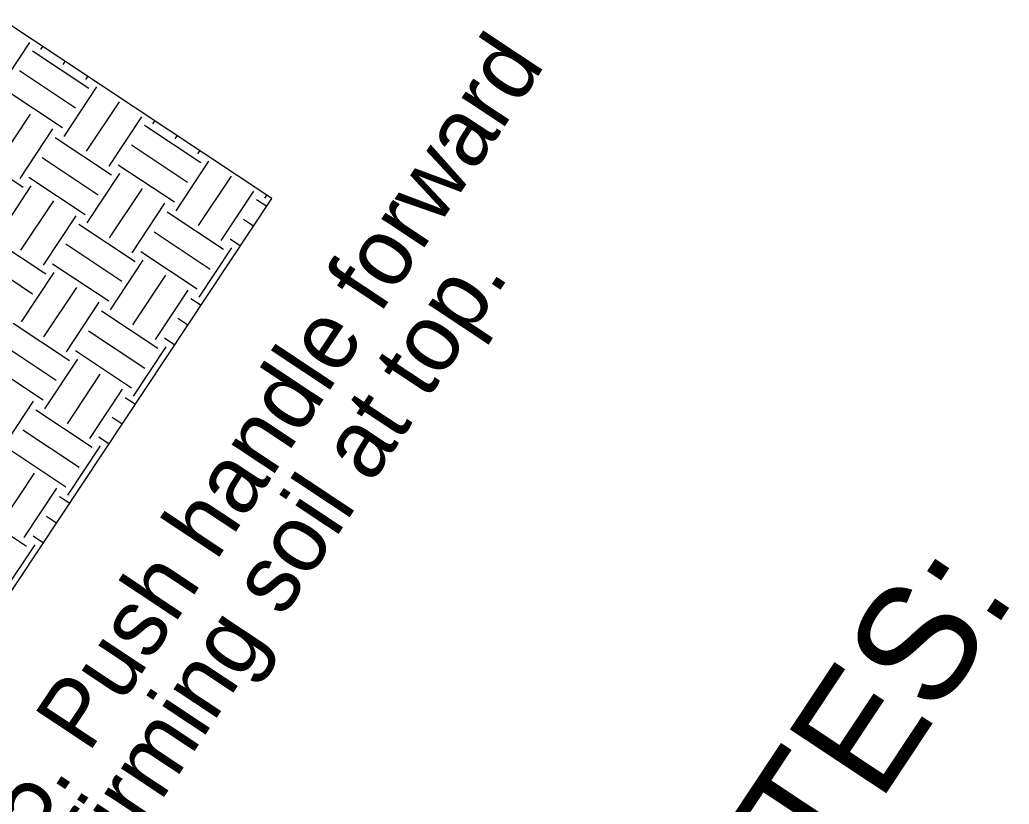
# Model space of a CAD drawing. Extents: x 561231 to 564935, y 589159 to 602519.
# Drawn here: x 564402.2 to 564461.1, y 589653.5 to 589700.2 of the extents above; entities that cross this region are included whole.
import ezdxf

# ---------------------------------------------------------------- set-up
doc = ezdxf.new("R2010")
doc.units = 0
doc.layers.add('Old_Level_1', color=7, linetype='Continuous')

msp = doc.modelspace()

# ---------------------------------------------------------------- linework, layer by layer
at = {"layer": 'Old_Level_1'}
for p, q in [((564417.212, 589689.566), (564390.326, 589707.404)), ((564400.867, 589695.909), (564402.821, 589698.855)), ((564402.975, 589698.36), (564406.32, 589696.141)), ((564403.467, 589698.427), (564403.586, 589698.606)), ((564404.805, 589697.539), (564404.924, 589697.719)), ((564402.193, 589697.182), (564405.538, 589694.963)), ((564406.143, 589696.651), (564406.262, 589696.831)), ((564401.412, 589696.004), (564404.757, 589693.784)), ((564404.858, 589693.262), (564406.812, 589696.207)), ((564406.196, 589692.374), (564408.15, 589695.32)), ((564400.898, 589691.648), (564402.851, 589694.593)), ((564407.534, 589691.486), (564409.488, 589694.432)), ((564409.642, 589693.937), (564412.987, 589691.718)), ((564410.134, 589694.003), (564410.253, 589694.183)), ((564402.236, 589690.76), (564404.189, 589693.705)), ((564404.329, 589693.189), (564407.674, 589690.97)), ((564408.86, 589692.759), (564412.206, 589690.539)), ((564411.472, 589693.116), (564411.591, 589693.295)), ((564399.068, 589692.469), (564402.413, 589690.25)), ((564412.81, 589692.228), (564412.929, 589692.407)), ((564403.547, 589692.011), (564406.892, 589689.792)), ((564408.079, 589691.58), (564411.424, 589689.361)), ((564411.525, 589688.839), (564413.479, 589691.784)), ((564406.226, 589688.112), (564408.18, 589691.058)), ((564402.766, 589690.833), (564406.111, 589688.613)), ((564412.863, 589687.951), (564414.817, 589690.896)), ((564400.952, 589687.37), (564402.905, 589690.316)), ((564407.565, 589687.225), (564409.518, 589690.17)), ((564414.202, 589687.063), (564416.155, 589690.009)), ((564393.99, 589654.55), (564417.212, 589689.566)), ((564402.289, 589686.483), (564404.243, 589689.429)), ((564408.903, 589686.337), (564410.856, 589689.282)), ((564416.309, 589689.514), (564416.912, 589689.114)), ((564416.8, 589689.58), (564416.92, 589689.76)), ((564410.996, 589688.766), (564414.341, 589686.546)), ((564403.628, 589685.595), (564405.581, 589688.541)), ((564405.735, 589688.046), (564409.08, 589685.826)), ((564415.527, 589688.336), (564416.131, 589687.935)), ((564410.214, 589687.588), (564413.559, 589685.368)), ((564400.421, 589687.298), (564403.767, 589685.079)), ((564404.953, 589686.867), (564408.299, 589684.648)), ((564414.746, 589687.157), (564415.349, 589686.757)), ((564409.433, 589686.409), (564412.778, 589684.19)), ((564412.894, 589683.689), (564414.847, 589686.635)), ((564399.64, 589686.12), (564402.985, 589683.9)), ((564404.172, 589685.689), (564407.517, 589683.47)), ((564407.618, 589682.947), (564409.572, 589685.893)), ((564402.32, 589682.221), (564404.273, 589685.167)), ((564408.956, 589682.059), (564410.91, 589685.005)), ((564403.658, 589681.333), (564405.611, 589684.279)), ((564410.295, 589681.172), (564412.248, 589684.117)), ((564404.996, 589680.446), (564406.949, 589683.391)), ((564412.402, 589683.623), (564413.005, 589683.222)), ((564407.088, 589682.875), (564410.434, 589680.655)), ((564401.828, 589682.154), (564405.173, 589679.935)), ((564411.62, 589682.444), (564412.223, 589682.044)), ((564406.307, 589681.696), (564409.652, 589679.477)), ((564401.046, 589680.976), (564404.391, 589678.757)), ((564410.839, 589681.266), (564411.442, 589680.866)), ((564405.526, 589680.518), (564408.871, 589678.299)), ((564408.987, 589677.798), (564410.94, 589680.743)), ((564400.265, 589679.798), (564403.61, 589677.579)), ((564403.711, 589677.056), (564405.665, 589680.002)), ((564405.05, 589676.168), (564407.003, 589679.114)), ((564406.388, 589675.28), (564408.341, 589678.226)), ((564401.089, 589674.554), (564403.042, 589677.5)), ((564408.495, 589677.731), (564409.098, 589677.331)), ((564403.182, 589676.983), (564406.527, 589674.764)), ((564407.713, 589676.553), (564408.316, 589676.153)), ((564402.4, 589675.805), (564405.746, 589673.586)), ((564406.932, 589675.375), (564407.535, 589674.975)), ((564401.619, 589674.627), (564404.964, 589672.408)), ((564405.08, 589671.906), (564407.033, 589674.852)), ((564401.143, 589670.277), (564403.096, 589673.223)), ((564402.481, 589669.389), (564404.434, 589672.335)), ((564404.588, 589671.84), (564405.191, 589671.44)), ((564399.275, 589671.092), (564402.62, 589668.873)), ((564403.807, 589670.662), (564404.41, 589670.262)), ((564403.025, 589669.484), (564403.628, 589669.084)), ((564401.173, 589666.015), (564403.127, 589668.961))]:
    msp.add_line(p, q, dxfattribs=at)

# ---------------------------------------------------------------- texts
for s, height, p in [('5. Push handle forward ', 4.01452, (564403.006, 589651.524)), (' firming soil at top.', 4.01452, (564407.308, 589648.671)), ('PLANTING NOTES:', 6.88204, (564415.781, 589596.869))]:
    msp.add_text(s, height=height, rotation=56.44825, dxfattribs=at).set_placement(p)

doc.saveas('drawing.dxf')
